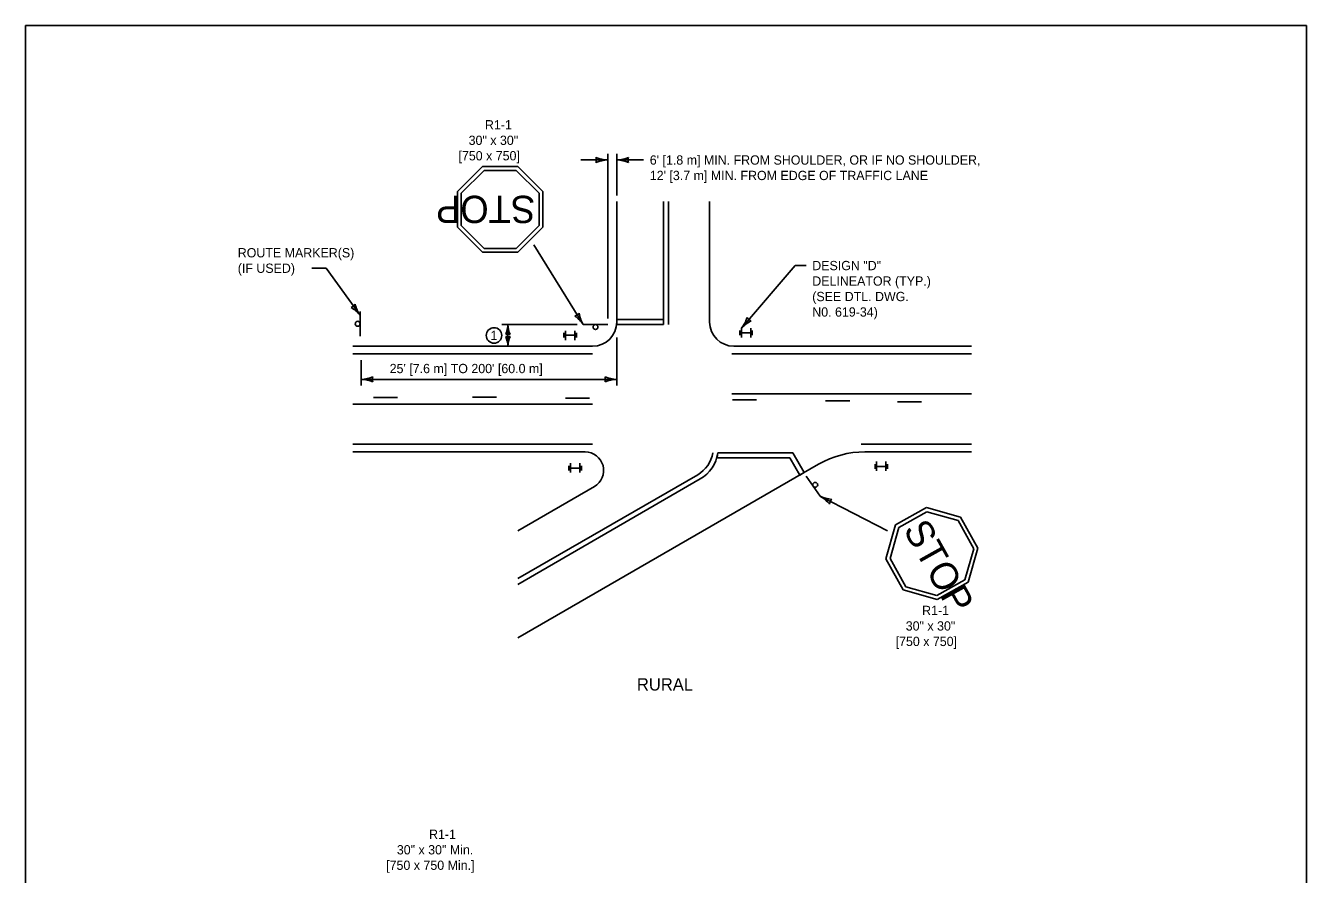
# Model space of a CAD drawing. Extents: x 49991.4 to 50021, y 49987.6 to 50011.4.
# Drawn here: x 50000.34 to 50008.61, y 50005.78 to 50011.26 of the extents above; entities that cross this region are included whole.
import ezdxf

# ---------------------------------------------------------------- set-up
doc = ezdxf.new("R2010")
doc.units = 0
for name, color, linetype in [('Level 1', 7, 'Continuous'), ('Level 2', 7, 'Continuous'), ('Level 3', 7, 'Continuous')]:
    doc.layers.add(name, color=color, linetype=linetype)

msp = doc.modelspace()

# ---------------------------------------------------------------- linework, layer by layer
at = {"layer": 'Level 1'}
for p, q in [((50003.2884, 50010.3518), (50003.1263, 50010.1897)), ((50003.2987, 50010.3268), (50003.1513, 50010.1794)), ((50003.5177, 50010.3518), (50003.2884, 50010.3518)), ((50003.5073, 50010.3268), (50003.2987, 50010.3268)), ((50003.5073, 50010.3268), (50003.6547, 50010.1794)), ((50003.5177, 50010.3518), (50003.6797, 50010.1898)), ((50003.1263, 50010.1897), (50003.1263, 50009.9606)), ((50003.1513, 50010.1794), (50003.1513, 50009.9708)), ((50003.6547, 50009.9708), (50003.6547, 50010.1794)), ((50003.6797, 50009.9605), (50003.6797, 50010.1898)), ((50004.157, 50009.3472), (50004.157, 50010.1258)), ((50004.4593, 50009.3316), (50004.4593, 50010.1258)), ((50004.4913, 50009.3316), (50004.4913, 50010.1258)), ((50004.757, 50009.3472), (50004.757, 50010.1258)), ((50003.2987, 50009.8234), (50003.1513, 50009.9708)), ((50003.5073, 50009.8234), (50003.6547, 50009.9708)), ((50003.2885, 50009.7984), (50003.1263, 50009.9606)), ((50003.5176, 50009.7984), (50003.6797, 50009.9605)), ((50003.2885, 50009.7984), (50003.5176, 50009.7984)), ((50003.2987, 50009.8234), (50003.5073, 50009.8234)), ((50002.498, 50009.2568), (50002.498, 50009.415)), ((50004.0984, 50009.3304), (50003.9402, 50009.3304)), ((50004.1562, 50009.3316), (50004.4593, 50009.3316)), ((50004.4593, 50009.3636), (50004.157, 50009.3636)), ((50004.157, 50009.3636), (50004.157, 50009.3472)), ((50004.4593, 50009.3316), (50004.4593, 50009.3636)), ((50004.9627, 50009.3069), (50004.9627, 50009.2469)), ((50005.0227, 50009.3069), (50005.0227, 50009.2469)), ((50003.815, 50009.2772), (50003.815, 50009.2473)), ((50003.8256, 50009.2909), (50003.8256, 50009.231)), ((50003.8857, 50009.2623), (50003.8256, 50009.2623)), ((50003.8857, 50009.2909), (50003.8857, 50009.231)), ((50003.896, 50009.2772), (50003.896, 50009.2473)), ((50004.9521, 50009.2933), (50004.9521, 50009.2632)), ((50005.0227, 50009.2783), (50004.9627, 50009.2783)), ((50005.0331, 50009.2933), (50005.0331, 50009.2632)), ((50004.0007, 50009.1909), (50002.4507, 50009.1909)), ((50004.0007, 50009.1409), (50002.4507, 50009.1409)), ((50006.4499, 50009.1409), (50004.9006, 50009.1409)), ((50006.4499, 50009.1909), (50004.9133, 50009.1909)), ((50004.0007, 50008.8159), (50002.4507, 50008.8159)), ((50002.739, 50008.8593), (50002.5834, 50008.8593)), ((50003.3793, 50008.8612), (50003.2237, 50008.8612)), ((50003.9809, 50008.8557), (50003.8253, 50008.8557)), ((50006.4499, 50008.8832), (50004.9006, 50008.8832)), ((50004.9053, 50008.8434), (50005.0609, 50008.8434)), ((50005.5069, 50008.8379), (50005.6625, 50008.8379)), ((50006.1265, 50008.8305), (50005.9709, 50008.8305)), ((50002.4507, 50008.5582), (50004.0007, 50008.5582)), ((50005.7362, 50008.5582), (50006.4499, 50008.5582)), ((50002.4507, 50008.5082), (50003.952, 50008.5082)), ((50005.2947, 50008.5015), (50004.81, 50008.5015)), ((50005.368, 50008.3744), (50005.2947, 50008.5015)), ((50005.7605, 50008.5082), (50006.4499, 50008.5082)), ((50003.5163, 50007.3053), (50005.4605, 50008.4278)), ((50003.8476, 50008.3886), (50003.8476, 50008.4186)), ((50003.858, 50008.3748), (50003.858, 50008.4349)), ((50003.858, 50008.4034), (50003.918, 50008.4034)), ((50003.918, 50008.3748), (50003.918, 50008.4349)), ((50003.9286, 50008.3886), (50003.9286, 50008.4186)), ((50004.8031, 50008.4695), (50005.2763, 50008.4695)), ((50005.2763, 50008.4695), (50005.3404, 50008.3584)), ((50005.8264, 50008.3987), (50005.8264, 50008.4287)), ((50005.8368, 50008.3849), (50005.8368, 50008.445)), ((50005.8368, 50008.4135), (50005.8969, 50008.4135)), ((50005.8969, 50008.3849), (50005.8969, 50008.445)), ((50005.9074, 50008.3987), (50005.9074, 50008.4287)), ((50003.5163, 50007.6886), (50004.6803, 50008.3607)), ((50003.5163, 50007.6517), (50004.6963, 50008.333)), ((50005.3404, 50008.3584), (50005.368, 50008.3744)), ((50005.3814, 50008.3511), (50005.4721, 50008.2214)), ((50003.5163, 50007.9981), (50004.012, 50008.2843)), ((50006.1589, 50008.148), (50005.9587, 50008.0362)), ((50006.3796, 50008.0854), (50006.1589, 50008.148)), ((50006.1621, 50008.1212), (50005.9801, 50008.0194)), ((50006.3627, 50008.0643), (50006.1621, 50008.1212)), ((50006.4644, 50007.8822), (50006.3627, 50008.0643)), ((50006.4912, 50007.8855), (50006.3796, 50008.0854)), ((50005.8964, 50007.8157), (50005.9587, 50008.0362)), ((50005.9233, 50007.8189), (50005.9801, 50008.0194)), ((50005.8964, 50007.8157), (50006.0081, 50007.6156)), ((50005.9233, 50007.8189), (50006.025, 50007.6367)), ((50006.4644, 50007.8822), (50006.4076, 50007.6817)), ((50006.4912, 50007.8855), (50006.4287, 50007.6649)), ((50006.2255, 50007.5799), (50006.4076, 50007.6817)), ((50006.2288, 50007.5531), (50006.4287, 50007.6649)), ((50006.0081, 50007.6156), (50006.2288, 50007.5531)), ((50006.025, 50007.6367), (50006.2255, 50007.5799))]:
    msp.add_line(p, q, dxfattribs=at)
msp.add_lwpolyline([(50008.6146, 50011.2628), (50000.3356, 50011.2628), (50000.3356, 50000.0624), (50008.6146, 50000.0624)], close=True, dxfattribs=at)
for centre, radius in [((50002.4821, 50009.3359), 0.0159), ((50004.0194, 50009.3146), 0.0158), ((50005.4397, 50008.2953), 0.0158)]:
    msp.add_circle(centre, radius, dxfattribs=at)
for centre, radius, start, end in [((50004.0007, 50009.3472), 0.1563, 270, 0), ((50004.0007, 50009.3472), 0.1563, 354.27188, 0), ((50004.9133, 50009.3472), 0.1563, 180, 270), ((50003.952, 50008.3882), 0.12, 299.99933, 90), ((50004.5803, 50008.5339), 0.2, 300.00073, 350.67851), ((50004.5803, 50008.5339), 0.2319, 300.00073, 351.97025), ((50004.5803, 50008.5339), 0.2319, 343.88001, 351.97025), ((50005.7605, 50007.9082), 0.6, 90, 119.99984)]:
    msp.add_arc(centre, radius, start, end, dxfattribs=at)
at = {"layer": 'Level 2'}
msp.add_circle((50003.3634, 50009.2605), 0.05, dxfattribs=at)
at = {"layer": 'Level 3'}
for p, q in [((50003.925, 50010.3944), (50004.0984, 50010.3944)), ((50004.0984, 50009.3704), (50004.0984, 50010.4344)), ((50004.157, 50010.1658), (50004.157, 50010.4344)), ((50004.157, 50010.3944), (50004.3304, 50010.3944)), ((50003.9402, 50009.3304), (50003.6198, 50009.8455)), ((50002.278, 50009.6949), (50002.1863, 50009.6949)), ((50002.498, 50009.3908), (50002.278, 50009.6949)), ((50004.9627, 50009.3069), (50005.3093, 50009.7121)), ((50005.3805, 50009.7121), (50005.3093, 50009.7121)), ((50003.4134, 50009.3304), (50003.9002, 50009.3304)), ((50003.4534, 50009.1909), (50003.4534, 50009.3304)), ((50004.157, 50008.9367), (50004.157, 50009.2472)), ((50002.5045, 50008.9367), (50002.5045, 50009.1009)), ((50002.5045, 50008.9767), (50004.157, 50008.9767)), ((50005.4721, 50008.2214), (50005.9072, 50007.9981))]:
    msp.add_line(p, q, dxfattribs=at)
for centre, radius, start, end in [((50004.1076, 50010.6165), 0.2223, 247.45601, 267.63952), ((50003.9702, 50010.3944), 0.0548, 342.13882, 17.86118), ((50004.1099, 50010.1617), 0.233, 92.82731, 112.07716), ((50004.1455, 50010.6271), 0.233, 272.82731, 292.07716), ((50004.1478, 50010.1723), 0.2223, 67.45601, 87.63952), ((50004.2852, 50010.3944), 0.0548, 162.13882, 197.86118), ((50002.4217, 50009.4938), 0.0548, 288.67063, 324.39299), ((50002.3179, 50009.243), 0.233, 39.35912, 58.60897), ((50002.6819, 50009.5156), 0.2223, 193.98782, 214.17133), ((50003.8723, 50009.4392), 0.0548, 284.1062, 319.82856), ((50003.7489, 50009.1974), 0.233, 34.79469, 54.04454), ((50004.1335, 50009.4402), 0.2223, 189.42339, 209.6069), ((50003.2683, 50009.338), 0.1853, 337.45601, 357.63952), ((50003.6473, 50009.34), 0.1942, 182.82731, 202.07716), ((50004.7772, 50009.4478), 0.233, 322.78091, 342.03076), ((50005.1269, 50009.157), 0.2223, 117.40961, 137.59312), ((50005.0452, 50009.4051), 0.0548, 212.09242, 247.81478), ((50003.4534, 50009.2236), 0.0456, 72.13882, 107.86118), ((50003.4534, 50009.2977), 0.0456, 252.13882, 287.86118), ((50003.2595, 50009.1813), 0.1942, 2.82731, 22.07716), ((50003.6385, 50009.1833), 0.1853, 157.45601, 177.63952), ((50002.493, 50009.2094), 0.233, 272.82731, 292.07716), ((50002.4953, 50008.7546), 0.2223, 67.45601, 87.63952), ((50002.6327, 50008.9767), 0.0548, 162.13882, 197.86118), ((50004.1662, 50009.1988), 0.2223, 247.45601, 267.63952), ((50004.0288, 50008.9767), 0.0548, 342.13882, 17.86118), ((50004.1685, 50008.744), 0.233, 92.82731, 112.07716), ((50005.3606, 50008.0291), 0.2223, 39.71283, 59.89634), ((50005.5703, 50008.4327), 0.233, 245.08413, 264.33398), ((50005.5856, 50008.1617), 0.0548, 134.39564, 170.118)]:
    msp.add_arc(centre, radius, start, end, dxfattribs=at)

# ---------------------------------------------------------------- texts
at = {"layer": 'Level 1'}
for rotation, p in [(180, (50003.6301, 50010.1633)), (299.189, (50006.006, 50008.0058))]:
    msp.add_text('STOP', height=0.1764, rotation=rotation, dxfattribs=at).set_placement(p)
at = {"layer": 'Level 2'}
for s, height, p in [('R1-1', 0.06, (50003.3048, 50010.5918)), ('30" x 30"', 0.06, (50003.1993, 50010.4918)), ('[750 x 750]', 0.06, (50003.1337, 50010.3918)), ("6' [1.8 m] MIN. FROM SHOULDER, OR IF NO SHOULDER,", 0.06, (50004.3704, 50010.3644)), ("12' [3.7 m] MIN. FROM EDGE OF TRAFFIC LANE", 0.06, (50004.3704, 50010.2644)), ('ROUTE MARKER(S)', 0.06, (50001.7069, 50009.7649)), ('(IF USED)', 0.06, (50001.7069, 50009.6649)), ('DESIGN "D"', 0.06, (50005.4205, 50009.6821)), ('DELINEATOR (TYP.)', 0.06, (50005.4205, 50009.5821)), ('(SEE DTL. DWG.', 0.06, (50005.4205, 50009.4821)), ('N0. 619-34)', 0.06, (50005.4205, 50009.3821)), ('1', 0.06, (50003.3407, 50009.2305)), ("25' [7.6 m] TO 200' [60.0 m]", 0.06, (50002.6889, 50009.0167)), ('R1-1', 0.06, (50006.1305, 50007.4531)), ('30" x 30"', 0.06, (50006.0249, 50007.3531)), ('[750 x 750]', 0.06, (50005.9594, 50007.2531)), ('RURAL', 0.08, (50004.2872, 50006.9655)), ('R1-1', 0.06, (50002.9434, 50006.0065)), ('30" x 30" Min.', 0.06, (50002.7353, 50005.9065)), ('[750 x 750 Min.]', 0.06, (50002.6663, 50005.8065))]:
    msp.add_text(s, height=height, dxfattribs=at).set_placement(p)

doc.saveas('drawing.dxf')
